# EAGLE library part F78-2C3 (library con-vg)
CONNECTOR female, 78 pins + 2 coax, type C
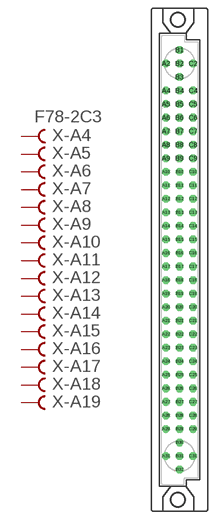
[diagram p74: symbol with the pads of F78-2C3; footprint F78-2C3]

Designator prefix X; gates -A4=FVAL -A5=FEM -A6=FEM -A7=FEM -A8=FEM -A9=FEM -A10=FEM -A11=FEM -A12=FEM -A13=FEM -A14=FEM -A15=FEM -A16=FEM -A17=FEM -A18=FEM -A19=FEM -A20=FEM -A21=FEM -A22=FEM -A23=FEM -A24=FEM -A25=FEM -A26=FEM -A27=FEM -A28=FEM -A29=FEM -B4=FVAL -B5=FEM -B6=FEM -B7=FEM -B8=FEM -B9=FEM -B10=FEM -B11=FEM -B12=FEM -B13=FEM -B14=FEM -B15=FEM -B16=FEM -B17=FEM -B18=FEM -B19=FEM -B20=FEM -B21=FEM -B22=FEM -B23=FEM -B24=FEM -B25=FEM -B26=FEM -B27=FEM -B28=FEM -B29=FEM -C4=FVAL -C5=FEM -C6=FEM -C7=FEM -C8=FEM -C9=FEM -C10=FEM -C11=FEM -C12=FEM -C13=FEM -C14=FEM -C15=FEM -C16=FEM -C17=FEM -C18=FEM -C19=FEM -C20=FEM -C21=FEM -C22=FEM -C23=FEM -C24=FEM -C25=FEM -C26=FEM -C27=FEM -C28=FEM -C29=FEM -1=COAX -2=COAX

## F78-2C3  [F78-2C3]
A2  -1:S3  pas
A4  -A4:B  pas
A5  -A5:B  pas
A6  -A6:B  pas
A7  -A7:B  pas
A8  -A8:B  pas
A9  -A9:B  pas
A10  -A10:B  pas
A11  -A11:B  pas
A12  -A12:B  pas
A13  -A13:B  pas
A14  -A14:B  pas
A15  -A15:B  pas
A16  -A16:B  pas
A17  -A17:B  pas
A18  -A18:B  pas
A19  -A19:B  pas
A20  -A20:B  pas
A21  -A21:B  pas
A22  -A22:B  pas
A23  -A23:B  pas
A24  -A24:B  pas
A25  -A25:B  pas
A26  -A26:B  pas
A27  -A27:B  pas
A28  -A28:B  pas
A29  -A29:B  pas
A31  -2:S3  pas
B1  -1:S1  pas
B2  -1:S  pas
B3  -1:S2  pas
B4  -B4:B  pas
B5  -B5:B  pas
B6  -B6:B  pas
B7  -B7:B  pas
B8  -B8:B  pas
B9  -B9:B  pas
B10  -B10:B  pas
B11  -B11:B  pas
B12  -B12:B  pas
B13  -B13:B  pas
B14  -B14:B  pas
B15  -B15:B  pas
B16  -B16:B  pas
B17  -B17:B  pas
B18  -B18:B  pas
B19  -B19:B  pas
B20  -B20:B  pas
B21  -B21:B  pas
B22  -B22:B  pas
B23  -B23:B  pas
B24  -B24:B  pas
B25  -B25:B  pas
B26  -B26:B  pas
B27  -B27:B  pas
B28  -B28:B  pas
B29  -B29:B  pas
B30  -2:S1  pas
B31  -2:S  pas
B32  -2:S2  pas
C2  -1:S4  pas
C4  -C4:B  pas
C5  -C5:B  pas
C6  -C6:B  pas
C7  -C7:B  pas
C8  -C8:B  pas
C9  -C9:B  pas
C10  -C10:B  pas
C11  -C11:B  pas
C12  -C12:B  pas
C13  -C13:B  pas
C14  -C14:B  pas
C15  -C15:B  pas
C16  -C16:B  pas
C17  -C17:B  pas
C18  -C18:B  pas
C19  -C19:B  pas
C20  -C20:B  pas
C21  -C21:B  pas
C22  -C22:B  pas
C23  -C23:B  pas
C24  -C24:B  pas
C25  -C25:B  pas
C26  -C26:B  pas
C27  -C27:B  pas
C28  -C28:B  pas
C29  -C29:B  pas
C31  -2:S4  pas

## Footprint F78-2C3 (pad centres in mm)
CONNECTOR female, 78 pins + 2 coax, type C
drill 0.914 octagon: A2 -2.54,36.83; A4 -2.54,31.75; A5 -2.54,29.21; A6 -2.54,26.67; A7 -2.54,24.13; A8 -2.54,21.59; A9 -2.54,19.05; A10 -2.54,16.51; A11 -2.54,13.97; A12 -2.54,11.43; A13 -2.54,8.89; A14 -2.54,6.35; A15 -2.54,3.81; A16 -2.54,1.27; A17 -2.54,-1.27; A18 -2.54,-3.81; A19 -2.54,-6.35; A20 -2.54,-8.89; A21 -2.54,-11.43; A22 -2.54,-13.97; A23 -2.54,-16.51; A24 -2.54,-19.05; A25 -2.54,-21.59; A26 -2.54,-24.13; A27 -2.54,-26.67; A28 -2.54,-29.21; A29 -2.54,-31.75; A31 -2.54,-36.83; B1 0,39.37; B2 0,36.83; B3 0,34.29; B4 0,31.75; B5 0,29.21; B6 0,26.67; B7 0,24.13; B8 0,21.59; B9 0,19.05; B10 0,16.51; B11 0,13.97; B12 0,11.43; B13 0,8.89; B14 0,6.35; B15 0,3.81; B16 0,1.27; B17 0,-1.27; B18 0,-3.81; B19 0,-6.35; B20 0,-8.89; B21 0,-11.43; B22 0,-13.97; B23 0,-16.51; B24 0,-19.05; B25 0,-21.59; B26 0,-24.13; B27 0,-26.67; B28 0,-29.21; B29 0,-31.75; B30 0,-34.29; B31 0,-36.83; B32 0,-39.37; C2 2.54,36.83; C4 2.54,31.75; C5 2.54,29.21; C6 2.54,26.67; C7 2.54,24.13; C8 2.54,21.59; C9 2.54,19.05; C10 2.54,16.51; C11 2.54,13.97; C12 2.54,11.43; C13 2.54,8.89; C14 2.54,6.35; C15 2.54,3.81; C16 2.54,1.27; C17 2.54,-1.27; C18 2.54,-3.81; C19 2.54,-6.35; C20 2.54,-8.89; C21 2.54,-11.43; C22 2.54,-13.97; C23 2.54,-16.51; C24 2.54,-19.05; C25 2.54,-21.59; C26 2.54,-24.13; C27 2.54,-26.67; C28 2.54,-29.21; C29 2.54,-31.75; C31 2.54,-36.83
hole 2.794 at -0.305,45.009
hole 2.794 at -0.305,-45.009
